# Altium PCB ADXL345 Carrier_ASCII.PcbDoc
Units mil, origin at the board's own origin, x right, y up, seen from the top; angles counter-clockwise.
Board outline 1250 x 1000 mil, 2 copper layers (Top Layer, Bottom Layer); 16 components, 14 nets, 63 pads, 10 vias.
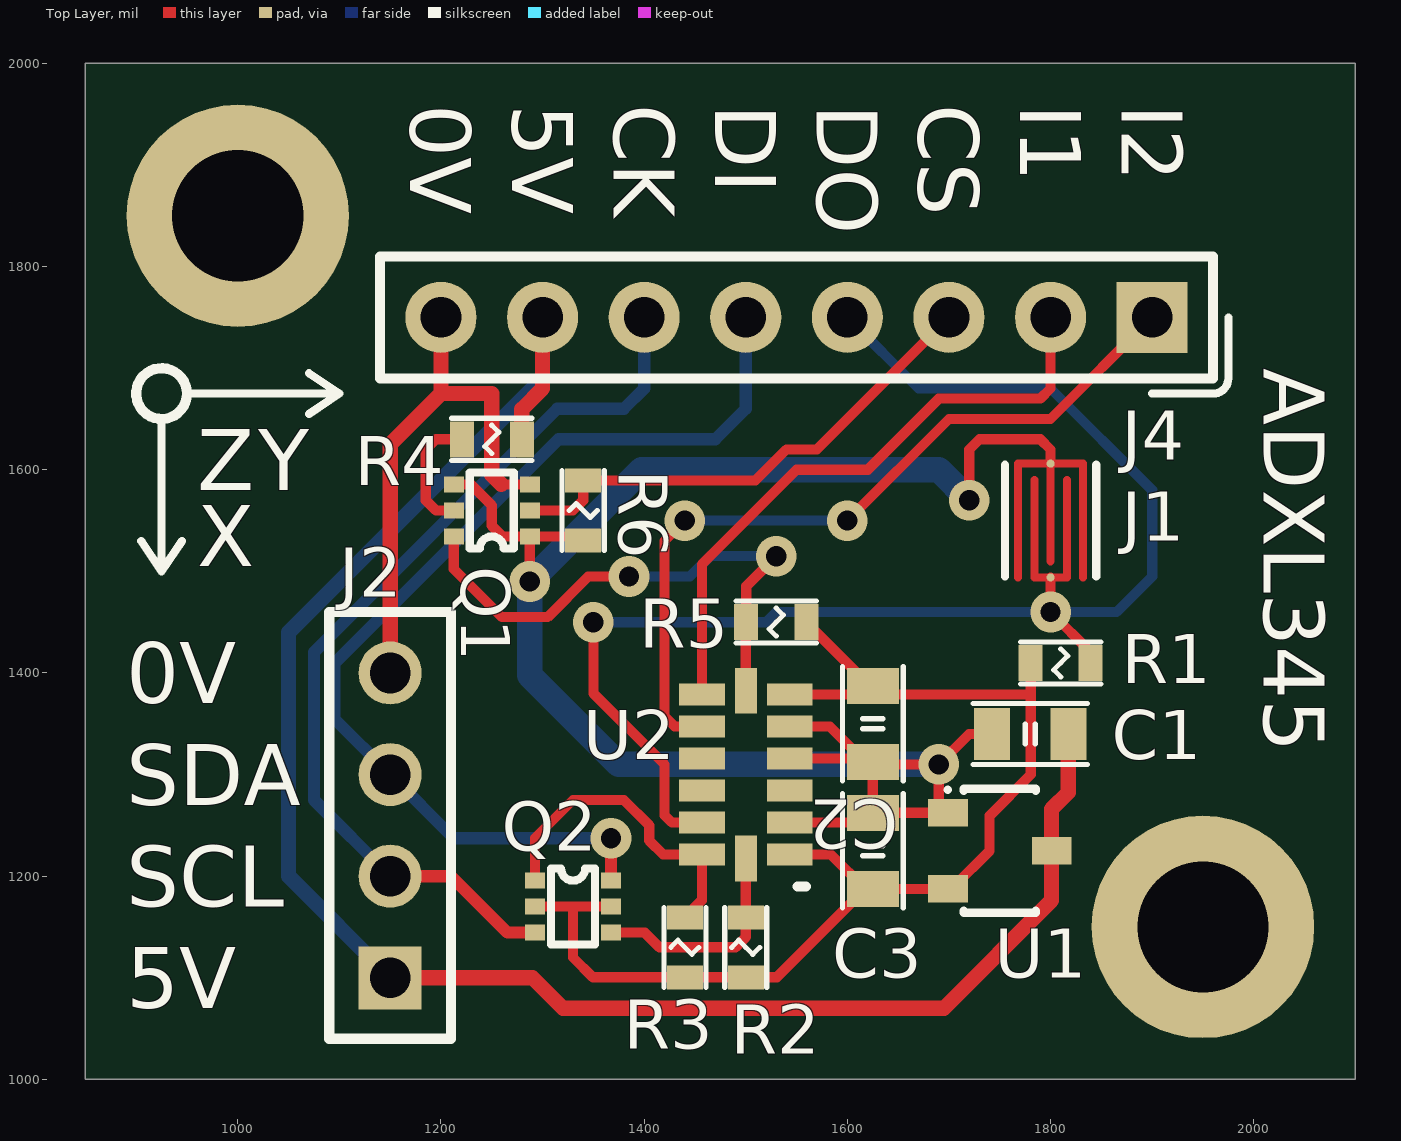
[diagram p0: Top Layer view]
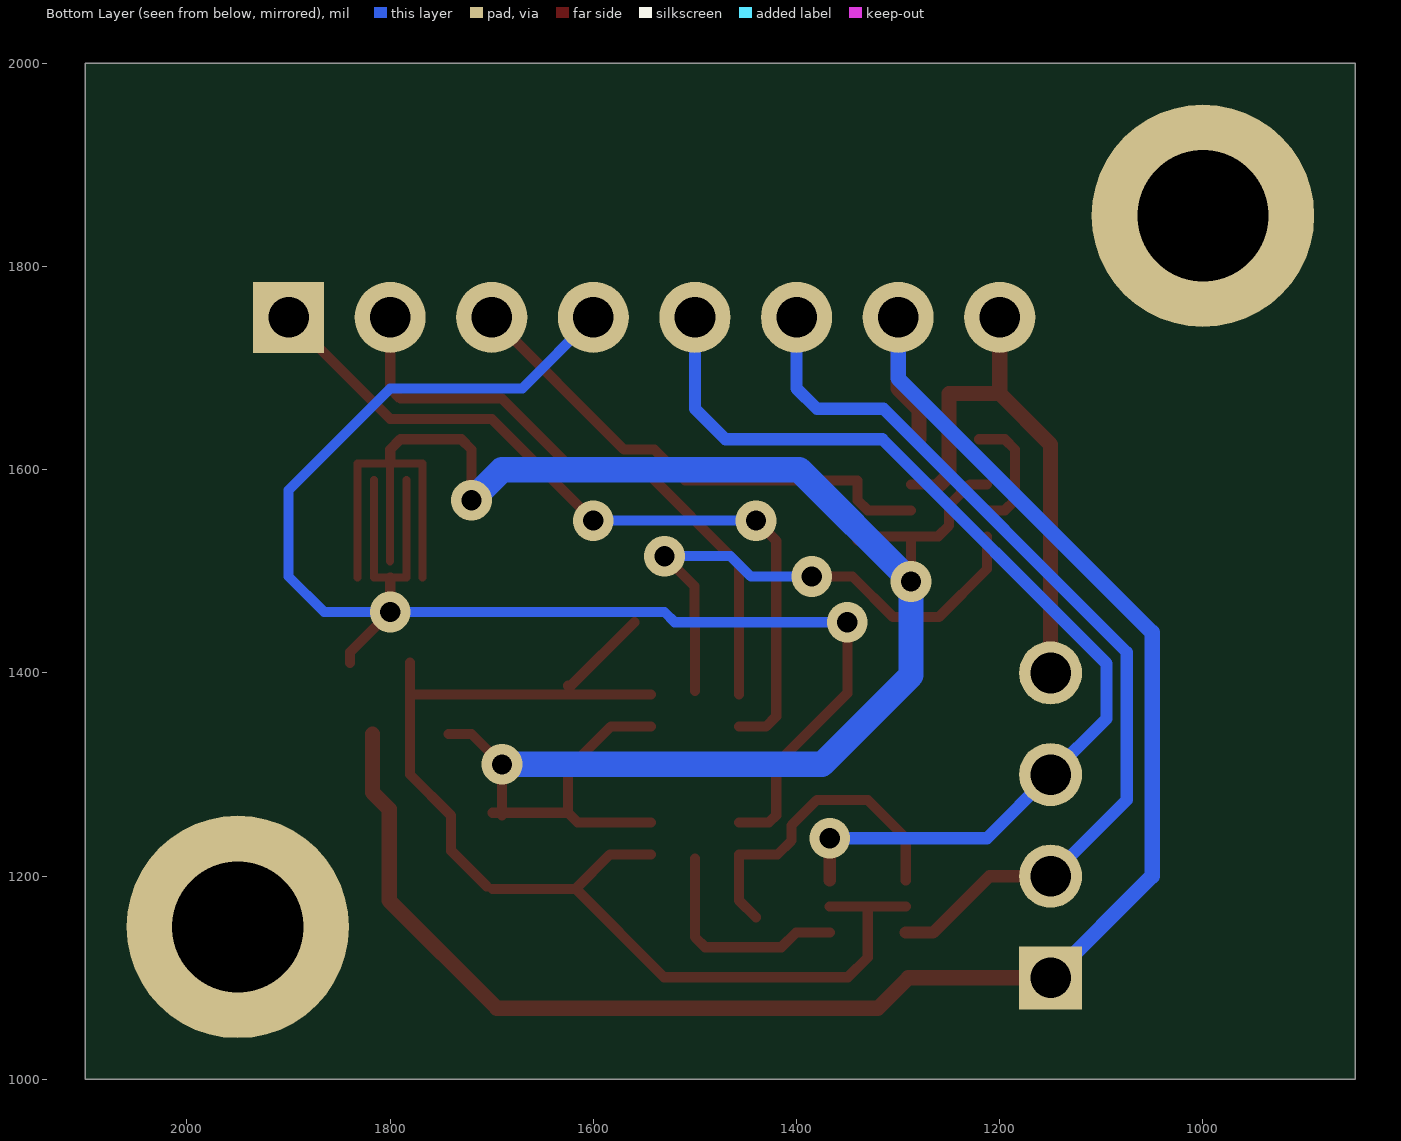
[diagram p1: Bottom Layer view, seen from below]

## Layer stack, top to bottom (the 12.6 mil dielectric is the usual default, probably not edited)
Top Layer: signal copper 1.4
Dielectric: dielectric 12.6, FR-4, Dk 4.8
Bottom Layer: signal copper 1.4

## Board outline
850,1000 850,2000 2100,2000 2100,1000

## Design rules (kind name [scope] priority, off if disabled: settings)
Clearance [All] p0: scope1count=1 scope1_0_kind=Board scope1_0_value=Board scope2count=1 scope2_0_kind=Board scope2_0_value=Board commentlength=0 gap=8
Clearance [All] p1: gap=8
ComponentClearance [All] p0: scope1count=1 scope1_0_kind=Board scope1_0_value=Board scope2count=1 scope2_0_kind=Board scope2_0_value=Board commentlength=0 gap=10 collisioncheckmode=3
DiffPairsRouting [All] p0: scope1count=1 scope1_0_kind=Board scope1_0_value=Board scope2count=1 scope2_0_kind=Board scope2_0_value=Board commentlength=0
FanoutControl Fanout_Default [All] p0: scope1count=1 scope1_0_kind=Board scope1_0_value=Board scope2count=1 scope2_0_kind=Board scope2_0_value=Board commentlength=30 // Fanout_Default (Default Rule)
FanoutControl Fanout_Small [All] p0 off: scope1count=1 scope1_0_kind=Board scope1_0_value=Board scope2count=1 scope2_0_kind=Board scope2_0_value=Board commentlength=84 // Protel DXP Scope 1 Expression Was: (CompPinCount < 5)   Fanout_Small (Default Rule)
FanoutControl Fanout_SOIC [All] p0 off: scope1count=1 scope1_0_kind=Board scope1_0_value=Board scope2count=1 scope2_0_kind=Board scope2_0_value=Board commentlength=71 // Protel DXP Scope 1 Expression Was: IsSOIC   Fanout_SOIC (Default Rule)
FanoutControl Fanout_LCC [All] p0 off: scope1count=1 scope1_0_kind=Board scope1_0_value=Board scope2count=1 scope2_0_kind=Board scope2_0_value=Board commentlength=69 // Protel DXP Scope 1 Expression Was: IsLCC   Fanout_LCC (Default Rule)
FanoutControl Fanout_BGA [All] p0 off: scope1count=1 scope1_0_kind=Board scope1_0_value=Board scope2count=1 scope2_0_kind=Board scope2_0_value=Board commentlength=69 // Protel DXP Scope 1 Expression Was: IsBGA   Fanout_BGA (Default Rule)
Height [All] p0: scope1count=1 scope1_0_kind=Board scope1_0_value=Board scope2count=1 scope2_0_kind=Board scope2_0_value=Board commentlength=0
HoleSize [All] p0: scope1count=1 scope1_0_kind=Board scope1_0_value=Board scope2count=1 scope2_0_kind=Board scope2_0_value=Board commentlength=0 absolutevalues=TRUE maxlimit=100 minlimit=1 maxpercent=80.000 minpercent=20.000
LayerPairs [All] p0: scope1count=1 scope1_0_kind=Board scope1_0_value=Board scope2count=1 scope2_0_kind=Board scope2_0_value=Board commentlength=0 enforce=TRUE
PasteMaskExpansion [All] p0: scope1count=1 scope1_0_kind=Board scope1_0_value=Board scope2count=1 scope2_0_kind=Board scope2_0_value=Board commentlength=0 expansion=0
PlaneClearance [All] p0: scope1count=1 scope1_0_kind=Board scope1_0_value=Board scope2count=1 scope2_0_kind=Board scope2_0_value=Board commentlength=0 clearance=20
PlaneConnect [All] p0: scope1count=1 scope1_0_kind=Board scope1_0_value=Board scope2count=1 scope2_0_kind=Board scope2_0_value=Board commentlength=0 planeconnectstyle=Relief reliefexpansion=20 reliefentries=4 reliefconductorwidth=10 reliefairgap=10
PolygonConnect [All] p0: scope1count=1 scope1_0_kind=Board scope1_0_value=Board scope2count=1 scope2_0_kind=Board scope2_0_value=Board commentlength=0 connectstyle=Relief reliefconductorwidth=10 reliefentries=4 polygonreliefangle="90 Angle"
PolygonConnect [All] p1: connectstyle=Relief reliefconductorwidth=10 reliefentries=4 polygonreliefangle="90 Angle"
RoutingCorners [All] p0: scope1count=1 scope1_0_kind=Board scope1_0_value=Board scope2count=1 scope2_0_kind=Board scope2_0_value=Board commentlength=0 cornerstyle=45-Degree minsetback=100 maxsetback=100
RoutingLayers [All] p0: scope1count=1 scope1_0_kind=Board scope1_0_value=Board scope2count=1 scope2_0_kind=Board scope2_0_value=Board commentlength=0 top layer=Automatic bottom layer=Automatic
RoutingPriority [All] p0: scope1count=1 scope1_0_kind=Board scope1_0_value=Board scope2count=1 scope2_0_kind=Board scope2_0_value=Board commentlength=0
RoutingTopology [All] p0: scope1count=1 scope1_0_kind=Board scope1_0_value=Board scope2count=1 scope2_0_kind=Board scope2_0_value=Board commentlength=0 topology=Shortest
RoutingVias [All] p0: scope1count=1 scope1_0_kind=Board scope1_0_value=Board scope2count=1 scope2_0_kind=Board scope2_0_value=Board commentlength=0 holewidth=28 width=50 viastyle="Through Hole" minholewidth=20 minwidth=40 maxholewidth=28 maxwidth=50
RoutingVias [All] p1: holewidth=28 width=50 viastyle="Through Hole" minholewidth=20 minwidth=40 maxholewidth=28 maxwidth=50
ShortCircuit [All] p0: scope1count=1 scope1_0_kind=Board scope1_0_value=Board scope2count=1 scope2_0_kind=Board scope2_0_value=Board commentlength=0 allowed=FALSE
SolderMaskExpansion [All] p0: scope1count=1 scope1_0_kind=Board scope1_0_value=Board scope2count=1 scope2_0_kind=Board scope2_0_value=Board commentlength=0 expansion=4
SolderMaskExpansion [All] p1: expansion=4
TestPointUsage [All] p0: scope1count=1 scope1_0_kind=Board scope1_0_value=Board scope2count=1 scope2_0_kind=Board scope2_0_value=Board commentlength=0 valid=0 allowmultiple=FALSE
TestPointUsage [All] p1: valid=0 allowmultiple=FALSE
Testpoint [All] p0: scope1count=1 scope1_0_kind=Board scope1_0_value=Board scope2count=1 scope2_0_kind=Board scope2_0_value=Board commentlength=0 side=15 testpointundercomponent=TRUE minsize=40 maxsize=100 preferedsize=60 minholesize=0 maxholesize=40 preferedholesize=32 testpointgrid=1 style=1023 order=0-112345678
Testpoint [All] p1: side=15 testpointundercomponent=TRUE minsize=40 maxsize=100 preferedsize=60 minholesize=0 maxholesize=40 preferedholesize=32 testpointgrid=1 style=1023 order=0-112345678
UnRoutedNet [All] p0: scope1count=1 scope1_0_kind=Board scope1_0_value=Board scope2count=1 scope2_0_kind=Board scope2_0_value=Board commentlength=0
Width [All] p0: scope1count=1 scope1_0_kind=Board scope1_0_value=Board scope2count=1 scope2_0_kind=Board scope2_0_value=Board commentlength=0 maxlimit=25 minlimit=6 preferedwidth=10
Width [All] p1: maxlimit=25 minlimit=6 preferedwidth=10
19 further rules are at their usual default settings.

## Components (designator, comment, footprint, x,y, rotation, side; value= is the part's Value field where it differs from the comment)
C1 "0.1uF 0805 Bypass" C0805_C 1780,1340 r0 top
C2 "4.7uF 0805 25V X5R" C0805_C 1625,1350 r270 top
C3 "0.1uF 0805 Bypass" C0805_C 1625,1225 r270 top
J1 "SolderBridge" "Solder Bridge" 1800,1550 r90 top
J2 "THRU VERT" H100P4 1150,1100 r90 top
J4 "THRU VERT" H100P1x8 1900,1750 r180 top
Q1 "FDG6303N - Dual N-Channel, Digital FET" SC70-6 1250,1560 r90 top
Q2 "FDG6303N - Dual N-Channel, Digital FET" SC70-6 1330,1170 r270 top
R1 "10k ohm 0603 1%" R0603_C 1810,1410 r180 top
R2 "3.16k ohm 0603 1%" R0603_C 1440,1130 r270 top
R3 "3.16k ohm 0603 1%" R0603_C 1500,1130 r270 top
R4 "10k ohm 0603 1%" R0603_C 1250,1630 r0 top
R5 "3.16k ohm 0603 1%" R0603_C 1530,1450 r0 top
R6 "100k ohm 0603 1%" R0603_C 1340,1560 r90 top
U1 "MCP1702T-3302E/CB" SOT-23-3 1750,1225 r0 top
U2 "ADXL345" ADXL345 1500,1300 r180 top

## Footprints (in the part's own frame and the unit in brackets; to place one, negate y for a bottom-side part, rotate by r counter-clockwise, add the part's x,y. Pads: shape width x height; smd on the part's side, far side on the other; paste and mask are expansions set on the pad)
ADXL345 [mm] "3-Axis, ±2 g/±4 g/±8 g/±16 g  Digital Accelerometer"
  rect 1.145x0.55 smd: 1(-1.097,2) 2(-1.097,1.2) 3(-1.097,0.4) 4(-1.097,-0.4) 5(-1.097,-1.2) 6(-1.097,-2) 8(1.097,-2) 9(1.097,-1.2) 10(1.097,-0.4) 11(1.097,0.4) 12(1.097,1.2) 13(1.097,2)
  rect 0.55x1.145 smd: 7(0,-2.097) 14(0,2.097)
  silkscreen extent -1.5,2.8 -1.3,2.8
C0805_C [mm]
  rect 0.9x1.3 smd: 1(-0.95,0) 2(0.95,0)
  silkscreen extent -1.42,-0.76 1.42,0.76
H100P1x8 [mil] "Header 100mil, 1x8POS THRU VERT"
  rect 70x70 hole 40: 1(0,0)
  round 70 hole 40: 2(100,0) 3(200,0) 4(300,0) 5(400,0) 6(500,0) 7(600,0) 8(700,0)
  silkscreen extent -75,-60 760,75
H100P4 [mil] "Header 100mil, 4POS THRU VERT"
  rect 62x62 hole 40: 1(0,0)
  round 62 hole 40: 2(100,0) 3(200,0) 4(300,0)
  silkscreen extent -60,-60 360,60
R0603_C [mm]
  rect 0.6x0.9 smd: 1(-0.75,0) 2(0.75,0)
  silkscreen extent -1,-0.53 1,0.53
SC70-6 [mm]
  rect 0.4x0.5 smd: 1(-0.65,-0.95) 2(0,-0.95) 3(0.65,-0.95) 4(0.65,0.95) 5(0,0.95) 6(-0.65,0.95)
  silkscreen extent -0.95,-0.55 0.95,0.55
"Solder Bridge" [mil]
  round 8 smd: 1(56,0) 2(-56,0)
  Top Layer lines w8: -56,32 56,32 56,0 ; 40,16 -56,16 -56,0 -56,-16 40,-16 ; -56,-32 56,-32 56,0 ; 56,0 -40,0 56,0
  silkscreen extent -55,-45 55,45
SOT-23-3 [mil]
  rect 39x27 smd: 1(-51,37.5) 2(-51,-37.5) 3(51,0)
  silkscreen extent -53,-61 35,62

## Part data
C2: library part "0.1uF 0805 Bypass", "0.1uF 0805 Bypass"
J2: library part "H100 1x6 THRU VERT", "1x6 Bird Pins"
J4: library part "H100 2x8 THRU VERT", "2x8 RA Birds"
Q1: library part "FDG6301N - Dual N (TINY)", "25V Dual N Channel Signal MOSFETS"
Q2: library part FDV301N, "N-Ch Logic FET, 25V, 0.22A, 5 Ohm"
R1: library part "3.16k ohm 0603 1%", "3.16k ohm 0603 1%"
U1: library part TC1015-3.3V, "3.3V 100mA Linear Regulator"
U2: "Small, Low Power, 3-Axis +/-3g iMEMS Accelerometer"

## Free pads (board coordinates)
  round 219 hole 129: MH(1000,1850) MH(1950,1150)

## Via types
v1: diameter 40, hole 20, Top Layer to Bottom Layer, 10 vias

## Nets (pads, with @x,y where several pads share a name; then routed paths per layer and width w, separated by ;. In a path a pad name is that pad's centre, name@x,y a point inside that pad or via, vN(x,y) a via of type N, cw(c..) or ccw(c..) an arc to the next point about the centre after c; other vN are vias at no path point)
3V3: C2.1 C3.2 Q2.2 Q2.5 R1.2 R2.2 R3.2 R5.2 U1.2 U2.1 U2.6 | length 1206.1
  Top Layer w10: Q2.2 1330,1170 ; Q2.5 1330,1170 ; U2.1 1583.74,1221.26 C3.2@1617.5,1187.5 ; U2.6 1625,1378.74 1780.47,1378.74 ; R5.2 1622.13,1387.4 C2.1 ; U1.2 1625,1187.5 C3.2@1617.5,1187.5 ; U1.2@1705,1190 1740,1225 1740,1259.53 1780.47,1300 1780.47,1378.74 ; R1.2 1780.47,1378.74 ; 1330,1170 1330,1120 1349.53,1100.47 R2.2 R3.2 1530.47,1100.47 C3.2@1617.5,1187.5
5V: C1.2 J2.1 J4.7 R4.2 U1.3 | length 1801.6
  Top Layer w15: J2.1 1290,1100 1320,1070 1695,1070 1801,1176 U1.3 1801,1266 1817.4,1282.4 C1.2 ; R4.2 1279.53,1659.53 1300,1680 J4.7
  Bottom Layer w15: J2.1 1050,1200 1050,1440 1300,1690 J4.7
\CS: Q1.6 R5.1 U2.7 | length 538.7
  Top Layer w10: Q1.6 1212.6,1502.4 1260,1455 1305,1455 1345,1495 v1(1385,1495) ; U2.7 1500,1449.53 R5.1 1500.47,1485.47 v1(1530,1515)
  Bottom Layer w10: v1(1385,1495) 1445,1495 1465,1515 v1(1530,1515)
CGND: J2.4 J4.8 Q1.3 | length 542
  Top Layer w10: 1259.41,1585.59 Q1.3
  Top Layer w15: J2.4 1150,1625 1200,1675 ; J4.8 1200,1675 ; 1259.41,1585.59 1250,1595 1250,1675 1200,1675
GND: C1.1 C2.2 C3.1 J1.1 Q1.1 Q1.4 R6.1 U1.1 U2.2 U2.4 U2.5 | length 1939.9
  Top Layer w10: Q1.4 1229.41,1585.59 1250,1565 1250,1545 1260.59,1534.41 Q1.1 ; v1(1287.4,1490) Q1.1 ; R6.1 1336.06,1534.41 Q1.1 ; U2.2 1615.35,1252.76 C3.1 ; U2.4 C2.2@1614.25,1315.75 ; U2.5 1582.76,1347.24 C2.2@1614.25,1315.75 ; C2.2@1615,1315 C2.2@1614.25,1315.75 ; U1.1@1690,1260 U1.1@1690,1262.5 ; U1.1 U1.1@1690,1262.5 ; v1(1720,1570) 1720,1620 1730,1630 1790,1630 1800,1620 J1.1 ; C1.1 1720,1340 v1(1690,1310) ; C2.2@1614.25,1315.75 1621.85,1315.75 C2.2 ; C3.1 C2.2 ; C3.1 1625.1,1262.5 U1.1@1690,1262.5 ; C2.2 1627.6,1310 v1(1690,1310) ; U1.1@1690,1262.5 v1(1690,1310)
  Bottom Layer w25: v1(1690,1310) 1375,1310 1287.4,1397.6 v1(1287.4,1490) 1397.4,1600 1690,1600 v1(1720,1570)
INT1: J4.2 U2.8 | length 613
  Top Layer w10: U2.8 1456.79,1506.79 1550,1600 1620,1600 1690,1670 1790,1670 1800,1680 J4.2
INT2: J4.1 U2.9 | length 784.8
  Top Layer w10: v1(1440,1550) 1420,1530 1420,1357.24 1430,1347.24 U2.9 ; v1(1600,1550) 1700,1650 1800,1650 J4.1
  Bottom Layer w10: v1(1440,1550) v1(1600,1550)
NetQ1_5: Q1.5 R4.1 | length 121.4
  Top Layer w10: Q1.5 1195,1560 1185,1570 1185,1620 1195,1630 R4.1
SCL: Q2.4 R3.1 U2.14 | length 220.1
  Top Layer w10: Q2.4 1400.59,1144.41 1415,1130 1490,1130 1500,1140 R3.1 U2.14
SDA: Q2.1 R2.1 U2.13 | length 321.4
  Top Layer w10: Q2.1 1292.6,1237.6 1330,1275 1380,1275 1405,1250 1405,1235 1418.74,1221.26 U2.13 1456.79,1176.32 R2.1
"SDO/ADDRESS SELECT": J1.2 J4.4 R1.1 U2.12 | length 1383.2
  Top Layer w10: v1(1350,1450) 1350,1380 1420,1310 1420,1260 1427.24,1252.76 U2.12 ; J1.2 v1(1800,1460) 1839.53,1420.47 R1.1
  Bottom Layer w10: v1(1350,1450) 1520,1450 1530,1460 v1(1800,1460) 1865,1460 1900,1495 1900,1580 1800,1680 1670,1680 J4.4
XCS: J4.3 Q1.2 R6.2 | length 502.7
  Top Layer w10: Q1.2 1330,1560 1340,1570 R6.2 1509.53,1589.53 1540,1620 1570,1620 J4.3
XSCL: J2.2 J4.6 Q2.3 | length 919.7
  Top Layer w12: J2.2 1210,1200 1265.59,1144.41 Q2.3
  Bottom Layer w12: J2.2 1075,1275 1075,1420.47 1314.53,1660 1380,1660 1400,1680 J4.6
XSDA: J2.3 J4.5 Q2.6 | length 1016.1
  Top Layer w12: Q2.6 v1(1367.4,1237.4)
  Bottom Layer w12: v1(1367.4,1237.4) 1212.6,1237.4 J2.3 1095,1355 1095,1409.38 1315.62,1630 1470,1630 1500,1660 J4.5
pads on no net: U2.3 U2.10 U2.11

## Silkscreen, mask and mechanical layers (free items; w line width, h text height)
Top Overlay:
  circle w10: c925,1675 r25
  lines w8: 905,1530 925,1500 ; 925,1650 925,1500 ; 945,1530 925,1500 ; 950,1675 1100,1675 ; 1070,1655 1100,1675 ; 1070,1695 1100,1675
  text "0V" at 1170,1960 h60 r270
  text "5V" at 1270,1960 h60 r270
  text "CK" at 1370,1960 h60 r270
  text "DI" at 1470,1960 h60 r270
  text "DO" at 1570,1960 h60 r270
  text "CS" at 1670,1960 h60 r270
  text "I1" at 1770,1960 h60 r270
  text "I2" at 1870,1960 h60 r270
  text "ADXL345" at 2010,1700 h60 r270
  text "Z" at 960,1580 h60
  text "Y" at 1020,1580 h60
  text "X" at 960,1505 h60
  text "0V" at 890,1370 h60
  text "SDA" at 890,1270 h60
  text "SCL" at 890,1170 h60
  text "5V" at 890,1070 h60
Mechanical 1:
  lines w1.67: 3396.57,2095.48 7282.74,2095.48 ; 5031.63,865.18 5031.63,2082.15
  lines w8: 850,1000 2100,1000 2100,2000 850,2000 850,1000
  text "C" at 3423.21,2126.97 h148.77
  text "o" at 3523.24,2126.97 h148.77
  text "n" at 3599.92,2126.97 h148.77
  text "s" at 3676.61,2126.97 h148.77
  text "t" at 3746.63,2126.97 h148.77
  text "r" at 3784.97,2126.97 h148.77
  text "u" at 3831.65,2126.97 h148.77
  text "c" at 3908.33,2126.97 h148.77
  text "t" at 3978.35,2126.97 h148.77
  text "i" at 4016.69,2126.97 h148.77
  text "o" at 4046.7,2126.97 h148.77
  text "n" at 4123.38,2126.97 h148.77
  text "L" at 3423.21,1955.26 h148.77
  text "a" at 3499.9,1955.26 h148.77
  text "y" at 3576.58,1955.26 h148.77
  text "e" at 3641.6,1955.26 h148.77
  text "r" at 3718.28,1955.26 h148.77
  text "s" at 3764.96,1955.26 h148.77
  text "2" at 5064.93,1955.26 h148.77
  text "F" at 3423.21,1786.88 h148.77
  text "i" at 3508.23,1786.88 h148.77
  text "n" at 3538.24,1786.88 h148.77
  text "i" at 3614.93,1786.88 h148.77
  text "s" at 3644.93,1786.88 h148.77
  text "h" at 3714.95,1786.88 h148.77
  text "e" at 3791.64,1786.88 h148.77
  text "d" at 3868.32,1786.88 h148.77
  text "T" at 3983.35,1786.88 h148.77
  text "h" at 4070.04,1786.88 h148.77
  text "i" at 4146.72,1786.88 h148.77
  text "c" at 4176.73,1786.88 h148.77
  text "k" at 4246.75,1786.88 h148.77
  text "n" at 4318.43,1786.88 h148.77
  text "e" at 4395.12,1786.88 h148.77
  text "s" at 4471.8,1786.88 h148.77
  text "s" at 4541.82,1786.88 h148.77
  text "0" at 5064.93,1786.88 h148.77
  text "6" at 5141.61,1786.88 h148.77
  text "2" at 5218.3,1786.88 h148.77
  text "+" at 5333.33,1786.88 h148.77
  text "/" at 5413.35,1786.88 h148.77
  text "-" at 5451.69,1786.88 h148.77
  text "3" at 5536.71,1786.88 h148.77
  text "0" at 5613.4,1786.88 h148.77
  text "%" at 5690.08,1786.88 h148.77
  text "S" at 3423.21,1591.84 h148.77
  text "o" at 3514.9,1591.84 h148.77
  text "l" at 3591.59,1591.84 h148.77
  text "d" at 3621.59,1591.84 h148.77
  text "e" at 3698.28,1591.84 h148.77
  text "r" at 3774.97,1591.84 h148.77
  text "M" at 3859.99,1591.84 h148.77
  text "a" at 3975.01,1591.84 h148.77
  text "s" at 4051.7,1591.84 h148.77
  text "k" at 4121.72,1591.84 h148.77
  text "U" at 5064.93,1591.84 h148.77
  text "n" at 5164.95,1591.84 h148.77
  text "s" at 5241.64,1591.84 h148.77
  text "p" at 5311.66,1591.84 h148.77
  text "e" at 5388.34,1591.84 h148.77
  text "c" at 5465.03,1591.84 h148.77
  text "i" at 5535.04,1591.84 h148.77
  text "f" at 5565.05,1591.84 h148.77
  text "i" at 5605.06,1591.84 h148.77
  text "e" at 5635.07,1591.84 h148.77
  text "d" at 5711.75,1591.84 h148.77
  text "C" at 5826.78,1591.84 h148.77
  text "o" at 5926.81,1591.84 h148.77
  text "l" at 6003.49,1591.84 h148.77
  text "o" at 6033.5,1591.84 h148.77
  text "r" at 6110.19,1591.84 h148.77
  text "T" at 5064.93,1420.13 h148.77
  text "o" at 5151.62,1420.13 h148.77
  text "p" at 5228.3,1420.13 h148.77
  text "&" at 5343.33,1420.13 h148.77
  text "B" at 5473.36,1420.13 h148.77
  text "o" at 5565.05,1420.13 h148.77
  text "t" at 5641.74,1420.13 h148.77
  text "t" at 5680.08,1420.13 h148.77
  text "o" at 5718.42,1420.13 h148.77
  text "m" at 5795.11,1420.13 h148.77
  text "S" at 3423.21,1248.42 h148.77
  text "i" at 3514.9,1248.42 h148.77
  text "l" at 3544.91,1248.42 h148.77
  text "k" at 3574.92,1248.42 h148.77
  text "S" at 3684.94,1248.42 h148.77
  text "c" at 3776.63,1248.42 h148.77
  text "r" at 3846.65,1248.42 h148.77
  text "e" at 3893.33,1248.42 h148.77
  text "e" at 3970.01,1248.42 h148.77
  text "n" at 4046.7,1248.42 h148.77
  text "U" at 5064.93,1248.42 h148.77
  text "n" at 5164.95,1248.42 h148.77
  text "s" at 5241.64,1248.42 h148.77
  text "p" at 5311.66,1248.42 h148.77
  text "e" at 5388.34,1248.42 h148.77
  text "c" at 5465.03,1248.42 h148.77
  text "i" at 5535.04,1248.42 h148.77
  text "f" at 5565.05,1248.42 h148.77
  text "i" at 5605.06,1248.42 h148.77
  text "e" at 5635.07,1248.42 h148.77
  text "d" at 5711.75,1248.42 h148.77
  text "C" at 5826.78,1248.42 h148.77
  text "o" at 5926.81,1248.42 h148.77
  text "l" at 6003.49,1248.42 h148.77
  text "o" at 6033.5,1248.42 h148.77
  text "r" at 6110.19,1248.42 h148.77
  text "T" at 5064.93,1076.71 h148.77
  text "o" at 5151.62,1076.71 h148.77
  text "p" at 5228.3,1076.71 h148.77
  text "O" at 5343.33,1076.71 h148.77
  text "n" at 5451.69,1076.71 h148.77
  text "l" at 5528.38,1076.71 h148.77
  text "y" at 5558.38,1076.71 h148.77
  text "-" at 5661.74,1076.71 h148.77
  text "I" at 5746.76,1076.71 h148.77
  text "g" at 5785.11,1076.71 h148.77
  text "n" at 5861.79,1076.71 h148.77
  text "o" at 5938.48,1076.71 h148.77
  text "r" at 6015.16,1076.71 h148.77
  text "e" at 6061.84,1076.71 h148.77
  text "B" at 6176.87,1076.71 h148.77
  text "o" at 6268.56,1076.71 h148.77
  text "t" at 6345.24,1076.71 h148.77
  text "t" at 6383.59,1076.71 h148.77
  text "o" at 6421.93,1076.71 h148.77
  text "m" at 6498.61,1076.71 h148.77
  text "S" at 6655.32,1076.71 h148.77
  text "i" at 6747.01,1076.71 h148.77
  text "l" at 6777.02,1076.71 h148.77
  text "k" at 6807.02,1076.71 h148.77
  text "C" at 3423.21,905 h148.77
  text "o" at 3523.24,905 h148.77
  text "p" at 3599.92,905 h148.77
  text "p" at 3676.61,905 h148.77
  text "e" at 3753.29,905 h148.77
  text "r" at 3829.98,905 h148.77
  text "W" at 3915,905 h148.77
  text "e" at 4053.37,905 h148.77
  text "i" at 4130.05,905 h148.77
  text "g" at 4160.06,905 h148.77
  text "h" at 4236.75,905 h148.77
  text "t" at 4313.43,905 h148.77
  text "1" at 5064.93,905 h148.77
  text "/" at 5141.61,905 h148.77
  text "2" at 5179.96,905 h148.77
  text "o" at 5294.98,905 h148.77
  text "z" at 5371.67,905 h148.77
  text "o" at 5476.7,905 h148.77
  text "r" at 5553.38,905 h148.77
  text "t" at 5638.4,905 h148.77
  text "h" at 5676.75,905 h148.77
  text "i" at 5753.43,905 h148.77
  text "c" at 5783.44,905 h148.77
  text "k" at 5853.46,905 h148.77
  text "e" at 5925.14,905 h148.77
  text "r" at 6001.83,905 h148.77
Drill Drawing:
  text ".legend" at 3400,2300 h60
